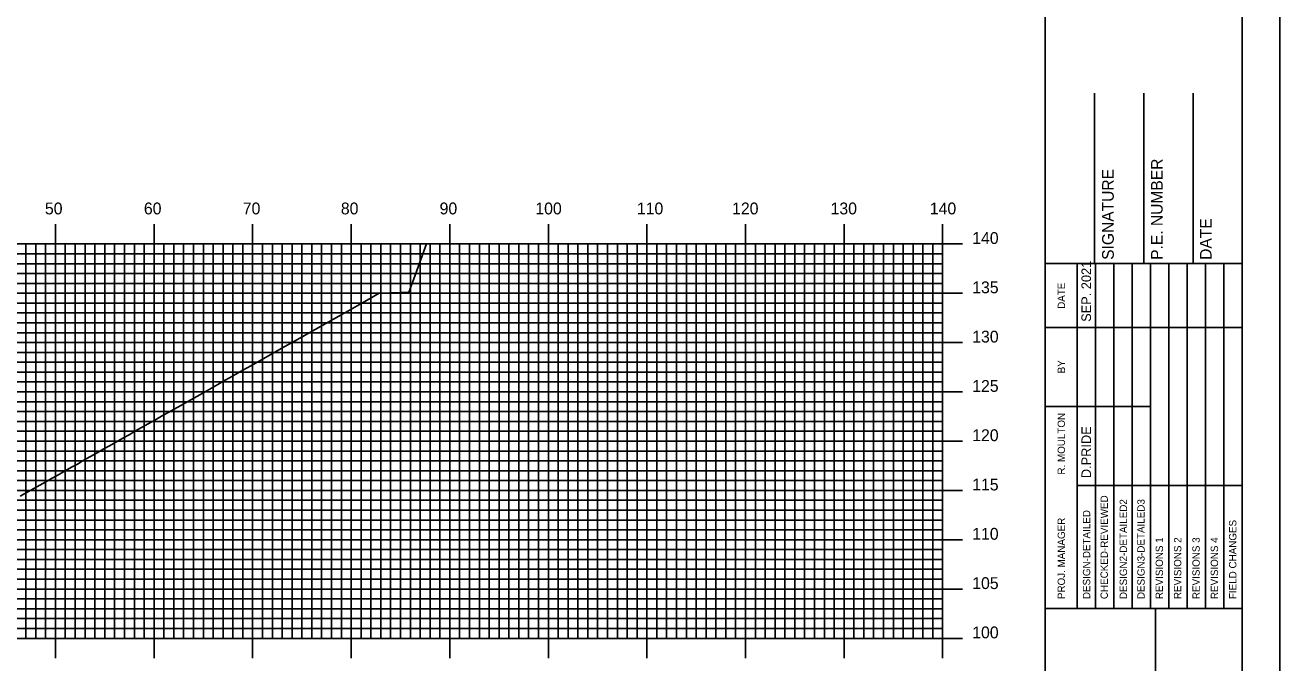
# Model space of a CAD drawing. Extents: x 1685192 to 1685536, y 461260 to 461480.
# Drawn here: x 1685405.1 to 1685532.4, y 461350.6 to 461415.3 of the extents above; entities that cross this region are included whole.
import ezdxf

# ---------------------------------------------------------------- set-up
doc = ezdxf.new("R2010")
doc.units = 0
for name, color, linetype in [('BORDER', 7, 'Continuous'), ('H_V ANNOTATION', 7, 'Continuous'), ('MAJOR', 7, 'Continuous'), ('MINOR', 7, 'Continuous'), ('PLOT BOUNDARY', 7, 'Continuous'), ('S_Roadway_Centerline', 7, 'Continuous')]:
    doc.layers.add(name, color=color, linetype=linetype)

msp = doc.modelspace()

# ---------------------------------------------------------------- linework, layer by layer
at = {"layer": 'BORDER'}
for p, q in [((1685508.63, 461266.07), (1685508.63, 461476.07)), ((1685513.63, 461391.08), (1685513.63, 461408.37)), ((1685518.63, 461391.08), (1685518.63, 461408.37)), ((1685523.63, 461391.08), (1685523.63, 461408.37)), ((1685508.63, 461391.08), (1685528.63, 461391.08)), ((1685508.63, 461356.08), (1685528.63, 461356.08)), ((1685519.81, 461286.08), (1685519.81, 461356.08))]:
    msp.add_line(p, q, dxfattribs=at)
msp.add_lwpolyline([(1685208.63, 461266.07), (1685528.63, 461266.07), (1685528.63, 461476.07), (1685208.63, 461476.07)], close=True, dxfattribs=at)
for points in [[(1685511.86, 461384.58), (1685511.86, 461391.08)], [(1685513.72, 461356.08), (1685513.72, 461391.08)], [(1685515.59, 461391.08), (1685515.59, 461356.08)], [(1685517.45, 461356.08), (1685517.45, 461391.08)], [(1685519.31, 461356.08), (1685519.31, 461391.08)], [(1685521.18, 461356.08), (1685521.18, 461391.08)], [(1685523.04, 461356.08), (1685523.04, 461391.08)], [(1685524.9, 461356.08), (1685524.9, 461391.08)], [(1685526.77, 461356.08), (1685526.77, 461391.08)], [(1685511.86, 461356.08), (1685511.86, 461389.67)], [(1685508.63, 461384.58), (1685528.63, 461384.58)], [(1685508.63, 461376.58), (1685511.86, 461376.58)], [(1685511.86, 461376.58), (1685519.31, 461376.58)], [(1685511.86, 461368.58), (1685528.63, 461368.58)]]:
    msp.add_lwpolyline(points, dxfattribs=at)
at = {"layer": 'MAJOR'}
for p, q in [((1685408.23, 461395.08), (1685408.23, 461393.07)), ((1685418.23, 461395.08), (1685418.23, 461393.07)), ((1685428.23, 461395.08), (1685428.23, 461393.07)), ((1685438.23, 461395.08), (1685438.23, 461393.07)), ((1685448.23, 461395.08), (1685448.23, 461393.07)), ((1685458.23, 461395.08), (1685458.23, 461393.07)), ((1685468.23, 461395.08), (1685468.23, 461393.07)), ((1685478.23, 461395.08), (1685478.23, 461393.07)), ((1685488.23, 461395.08), (1685488.23, 461393.07)), ((1685498.23, 461395.08), (1685498.23, 461393.07)), ((1685218.23, 461393.07), (1685498.23, 461393.07)), ((1685218.23, 461393.07), (1685498.23, 461393.07)), ((1685408.23, 461353.07), (1685408.23, 461393.07)), ((1685418.23, 461353.07), (1685418.23, 461393.07)), ((1685428.23, 461353.07), (1685428.23, 461393.07)), ((1685438.23, 461353.07), (1685438.23, 461393.07)), ((1685448.23, 461353.07), (1685448.23, 461393.07)), ((1685458.23, 461353.07), (1685458.23, 461393.07)), ((1685468.23, 461353.07), (1685468.23, 461393.07)), ((1685478.23, 461353.07), (1685478.23, 461393.07)), ((1685488.23, 461353.07), (1685488.23, 461393.07)), ((1685500.23, 461393.07), (1685496.23, 461393.07)), ((1685498.23, 461353.07), (1685498.23, 461393.07)), ((1685498.23, 461353.07), (1685498.23, 461393.07)), ((1685218.23, 461388.07), (1685498.23, 461388.07)), ((1685500.23, 461388.07), (1685496.23, 461388.07)), ((1685218.23, 461383.07), (1685498.23, 461383.07)), ((1685500.23, 461383.07), (1685496.23, 461383.07)), ((1685218.23, 461378.07), (1685498.23, 461378.07)), ((1685500.23, 461378.07), (1685496.23, 461378.07)), ((1685218.23, 461373.07), (1685498.23, 461373.07)), ((1685500.23, 461373.07), (1685496.23, 461373.07)), ((1685218.23, 461368.07), (1685498.23, 461368.07)), ((1685500.23, 461368.07), (1685496.23, 461368.07)), ((1685218.23, 461363.07), (1685498.23, 461363.07)), ((1685500.23, 461363.07), (1685496.23, 461363.07)), ((1685218.23, 461358.07), (1685498.23, 461358.07)), ((1685500.23, 461358.07), (1685496.23, 461358.07)), ((1685218.23, 461353.07), (1685498.23, 461353.07)), ((1685218.23, 461353.07), (1685498.23, 461353.07)), ((1685408.23, 461351.07), (1685408.23, 461353.07)), ((1685418.23, 461351.07), (1685418.23, 461353.07)), ((1685428.23, 461351.07), (1685428.23, 461353.07)), ((1685438.23, 461351.07), (1685438.23, 461353.07)), ((1685448.23, 461351.07), (1685448.23, 461353.07)), ((1685458.23, 461351.07), (1685458.23, 461353.07)), ((1685468.23, 461351.07), (1685468.23, 461353.07)), ((1685478.23, 461351.07), (1685478.23, 461353.07)), ((1685488.23, 461351.07), (1685488.23, 461353.07)), ((1685500.23, 461353.07), (1685496.23, 461353.07)), ((1685498.23, 461351.07), (1685498.23, 461353.07))]:
    msp.add_line(p, q, dxfattribs=at)
at = {"layer": 'MINOR'}
for p, q in [((1685405.23, 461353.07), (1685405.23, 461393.07)), ((1685406.23, 461353.07), (1685406.23, 461393.07)), ((1685407.23, 461353.07), (1685407.23, 461393.07)), ((1685409.23, 461353.07), (1685409.23, 461393.07)), ((1685410.23, 461353.07), (1685410.23, 461393.07)), ((1685411.23, 461353.07), (1685411.23, 461393.07)), ((1685412.23, 461353.07), (1685412.23, 461393.07)), ((1685413.23, 461353.07), (1685413.23, 461393.07)), ((1685414.23, 461353.07), (1685414.23, 461393.07)), ((1685415.23, 461353.07), (1685415.23, 461393.07)), ((1685416.23, 461353.07), (1685416.23, 461393.07)), ((1685417.23, 461353.07), (1685417.23, 461393.07)), ((1685419.23, 461353.07), (1685419.23, 461393.07)), ((1685420.23, 461353.07), (1685420.23, 461393.07)), ((1685421.23, 461353.07), (1685421.23, 461393.07)), ((1685422.23, 461353.07), (1685422.23, 461393.07)), ((1685423.23, 461353.07), (1685423.23, 461393.07)), ((1685424.23, 461353.07), (1685424.23, 461393.07)), ((1685425.23, 461353.07), (1685425.23, 461393.07)), ((1685426.23, 461353.07), (1685426.23, 461393.07)), ((1685427.23, 461353.07), (1685427.23, 461393.07)), ((1685429.23, 461353.07), (1685429.23, 461393.07)), ((1685430.23, 461353.07), (1685430.23, 461393.07)), ((1685431.23, 461353.07), (1685431.23, 461393.07)), ((1685432.23, 461353.07), (1685432.23, 461393.07)), ((1685433.23, 461353.07), (1685433.23, 461393.07)), ((1685434.23, 461353.07), (1685434.23, 461393.07)), ((1685435.23, 461353.07), (1685435.23, 461393.07)), ((1685436.23, 461353.07), (1685436.23, 461393.07)), ((1685437.23, 461353.07), (1685437.23, 461393.07)), ((1685439.23, 461353.07), (1685439.23, 461393.07)), ((1685440.23, 461353.07), (1685440.23, 461393.07)), ((1685441.23, 461353.07), (1685441.23, 461393.07)), ((1685442.23, 461353.07), (1685442.23, 461393.07)), ((1685443.23, 461353.07), (1685443.23, 461393.07)), ((1685444.23, 461353.07), (1685444.23, 461393.07)), ((1685445.23, 461353.07), (1685445.23, 461393.07)), ((1685446.23, 461353.07), (1685446.23, 461393.07)), ((1685447.23, 461353.07), (1685447.23, 461393.07)), ((1685449.23, 461353.07), (1685449.23, 461393.07)), ((1685450.23, 461353.07), (1685450.23, 461393.07)), ((1685451.23, 461353.07), (1685451.23, 461393.07)), ((1685452.23, 461353.07), (1685452.23, 461393.07)), ((1685453.23, 461353.07), (1685453.23, 461393.07)), ((1685454.23, 461353.07), (1685454.23, 461393.07)), ((1685455.23, 461353.07), (1685455.23, 461393.07)), ((1685456.23, 461353.07), (1685456.23, 461393.07)), ((1685457.23, 461353.07), (1685457.23, 461393.07)), ((1685459.23, 461353.07), (1685459.23, 461393.07)), ((1685460.23, 461353.07), (1685460.23, 461393.07)), ((1685461.23, 461353.07), (1685461.23, 461393.07)), ((1685462.23, 461353.07), (1685462.23, 461393.07)), ((1685463.23, 461353.07), (1685463.23, 461393.07)), ((1685464.23, 461353.07), (1685464.23, 461393.07)), ((1685465.23, 461353.07), (1685465.23, 461393.07)), ((1685466.23, 461353.07), (1685466.23, 461393.07)), ((1685467.23, 461353.07), (1685467.23, 461393.07)), ((1685469.23, 461353.07), (1685469.23, 461393.07)), ((1685470.23, 461353.07), (1685470.23, 461393.07)), ((1685471.23, 461353.07), (1685471.23, 461393.07)), ((1685472.23, 461353.07), (1685472.23, 461393.07)), ((1685473.23, 461353.07), (1685473.23, 461393.07)), ((1685474.23, 461353.07), (1685474.23, 461393.07)), ((1685475.23, 461353.07), (1685475.23, 461393.07)), ((1685476.23, 461353.07), (1685476.23, 461393.07)), ((1685477.23, 461353.07), (1685477.23, 461393.07)), ((1685479.23, 461353.07), (1685479.23, 461393.07)), ((1685480.23, 461353.07), (1685480.23, 461393.07)), ((1685481.23, 461353.07), (1685481.23, 461393.07)), ((1685482.23, 461353.07), (1685482.23, 461393.07)), ((1685483.23, 461353.07), (1685483.23, 461393.07)), ((1685484.23, 461353.07), (1685484.23, 461393.07)), ((1685485.23, 461353.07), (1685485.23, 461393.07)), ((1685486.23, 461353.07), (1685486.23, 461393.07)), ((1685487.23, 461353.07), (1685487.23, 461393.07)), ((1685489.23, 461353.07), (1685489.23, 461393.07)), ((1685490.23, 461353.07), (1685490.23, 461393.07)), ((1685491.23, 461353.07), (1685491.23, 461393.07)), ((1685492.23, 461353.07), (1685492.23, 461393.07)), ((1685493.23, 461353.07), (1685493.23, 461393.07)), ((1685494.23, 461353.07), (1685494.23, 461393.07)), ((1685495.23, 461353.07), (1685495.23, 461393.07)), ((1685496.23, 461353.07), (1685496.23, 461393.07)), ((1685497.23, 461353.07), (1685497.23, 461393.07)), ((1685218.23, 461392.07), (1685498.23, 461392.07)), ((1685498.23, 461392.07), (1685496.23, 461392.07)), ((1685218.23, 461391.07), (1685498.23, 461391.07)), ((1685498.23, 461391.07), (1685496.23, 461391.07)), ((1685218.23, 461390.07), (1685498.23, 461390.07)), ((1685498.23, 461390.07), (1685496.23, 461390.07)), ((1685218.23, 461389.07), (1685498.23, 461389.07)), ((1685498.23, 461389.07), (1685496.23, 461389.07)), ((1685218.23, 461387.07), (1685498.23, 461387.07)), ((1685498.23, 461387.07), (1685496.23, 461387.07)), ((1685218.23, 461386.07), (1685498.23, 461386.07)), ((1685498.23, 461386.07), (1685496.23, 461386.07)), ((1685218.23, 461385.07), (1685498.23, 461385.07)), ((1685218.23, 461384.07), (1685498.23, 461384.07)), ((1685498.23, 461385.07), (1685496.23, 461385.07)), ((1685498.23, 461384.07), (1685496.23, 461384.07)), ((1685218.23, 461382.07), (1685498.23, 461382.07)), ((1685498.23, 461382.07), (1685496.23, 461382.07)), ((1685218.23, 461381.07), (1685498.23, 461381.07)), ((1685498.23, 461381.07), (1685496.23, 461381.07)), ((1685218.23, 461380.07), (1685498.23, 461380.07)), ((1685218.23, 461379.07), (1685498.23, 461379.07)), ((1685498.23, 461380.07), (1685496.23, 461380.07)), ((1685498.23, 461379.07), (1685496.23, 461379.07)), ((1685218.23, 461377.07), (1685498.23, 461377.07)), ((1685498.23, 461377.07), (1685496.23, 461377.07)), ((1685218.23, 461376.07), (1685498.23, 461376.07)), ((1685498.23, 461376.07), (1685496.23, 461376.07)), ((1685218.23, 461375.07), (1685498.23, 461375.07)), ((1685218.23, 461374.07), (1685498.23, 461374.07)), ((1685498.23, 461375.07), (1685496.23, 461375.07)), ((1685498.23, 461374.07), (1685496.23, 461374.07)), ((1685218.23, 461372.07), (1685498.23, 461372.07)), ((1685498.23, 461372.07), (1685496.23, 461372.07)), ((1685218.23, 461371.07), (1685498.23, 461371.07)), ((1685218.23, 461370.07), (1685498.23, 461370.07)), ((1685498.23, 461371.07), (1685496.23, 461371.07)), ((1685498.23, 461370.07), (1685496.23, 461370.07)), ((1685218.23, 461369.07), (1685498.23, 461369.07)), ((1685498.23, 461369.07), (1685496.23, 461369.07)), ((1685218.23, 461367.07), (1685498.23, 461367.07)), ((1685498.23, 461367.07), (1685496.23, 461367.07)), ((1685218.23, 461366.07), (1685498.23, 461366.07)), ((1685218.23, 461365.07), (1685498.23, 461365.07)), ((1685498.23, 461366.07), (1685496.23, 461366.07)), ((1685498.23, 461365.07), (1685496.23, 461365.07)), ((1685218.23, 461364.07), (1685498.23, 461364.07)), ((1685498.23, 461364.07), (1685496.23, 461364.07)), ((1685218.23, 461362.07), (1685498.23, 461362.07)), ((1685498.23, 461362.07), (1685496.23, 461362.07)), ((1685218.23, 461361.07), (1685498.23, 461361.07)), ((1685218.23, 461360.07), (1685498.23, 461360.07)), ((1685498.23, 461361.07), (1685496.23, 461361.07)), ((1685498.23, 461360.07), (1685496.23, 461360.07)), ((1685218.23, 461359.07), (1685498.23, 461359.07)), ((1685498.23, 461359.07), (1685496.23, 461359.07)), ((1685218.23, 461357.07), (1685498.23, 461357.07)), ((1685218.23, 461356.07), (1685498.23, 461356.07)), ((1685498.23, 461357.07), (1685496.23, 461357.07)), ((1685498.23, 461356.07), (1685496.23, 461356.07)), ((1685218.23, 461355.07), (1685498.23, 461355.07)), ((1685498.23, 461355.07), (1685496.23, 461355.07)), ((1685218.23, 461354.07), (1685498.23, 461354.07)), ((1685498.23, 461354.07), (1685496.23, 461354.07))]:
    msp.add_line(p, q, dxfattribs=at)
at = {"layer": 'PLOT BOUNDARY'}
msp.add_lwpolyline([(1685192.44, 461259.95), (1685532.44, 461259.95), (1685532.44, 461479.95), (1685192.44, 461479.95)], close=True, dxfattribs=at)
at = {"layer": 'S_Roadway_Centerline'}
msp.add_lwpolyline([(1685404.66, 461367.48), (1685405.2, 461367.78), (1685405.74, 461368.09), (1685407.26, 461368.95), (1685407.82, 461369.27), (1685408.4, 461369.59), (1685409.86, 461370.42), (1685410.45, 461370.75), (1685411.05, 461371.1), (1685412.46, 461371.89), (1685413.07, 461372.24), (1685413.7, 461372.6), (1685415.05, 461373.36), (1685415.7, 461373.72), (1685416.35, 461374.1), (1685417.65, 461374.84), (1685418.32, 461375.21), (1685419, 461375.6), (1685420.26, 461376.31), (1685420.95, 461376.69), (1685421.65, 461377.09), (1685422.86, 461377.78), (1685423.57, 461378.18), (1685424.3, 461378.59), (1685425.46, 461379.25), (1685426.2, 461379.66), (1685426.94, 461380.09), (1685428.06, 461380.72), (1685428.82, 461381.14), (1685429.59, 461381.58), (1685430.66, 461382.19), (1685431.44, 461382.63), (1685432.23, 461383.08), (1685433.27, 461383.66), (1685436.98, 461385.75), (1685437.18, 461385.86), (1685437.32, 461385.94), (1685437.65, 461386.13), (1685439.53, 461387.2), (1685440.08, 461387.51), (1685441.08, 461388.07), (1685442.24, 461388.11), (1685444.08, 461388.17), (1685444.17, 461388.42), (1685444.18, 461388.45), (1685444.58, 461389.54), (1685445.87, 461393.07)], dxfattribs=at)

# ---------------------------------------------------------------- texts
at = {"layer": 'BORDER'}
for s, height, p in [('P.E. NUMBER', 1.1811, (1685520.55, 461391.46)), ('SIGNATURE', 1.181, (1685515.59, 461391.46)), ('DATE', 1.181, (1685525.51, 461391.46)), ('SEP. 2021', 0.969, (1685513.28, 461385.17)), ('DATE', 0.743, (1685510.64, 461386.49)), ('BY', 0.743, (1685510.64, 461379.95)), ('R. MOULTON', 0.745, (1685510.64, 461369.68)), ('D.PRIDE', 0.969, (1685513.28, 461369.32)), ('CHECKED-REVIEWED', 0.7455, (1685514.99, 461357.05)), ('DESIGN2-DETAILED2', 0.7455, (1685516.93, 461357.05)), ('DESIGN3-DETAILED3', 0.7455, (1685518.72, 461357.05)), ('PROJ. MANAGER', 0.7455, (1685510.64, 461357.05)), ('DESIGN-DETAILED', 0.7455, (1685513.2, 461357.05)), ('FIELD CHANGES', 0.7455, (1685528.03, 461357.05)), ('REVISIONS 1', 0.7455, (1685520.58, 461357.05)), ('REVISIONS 2', 0.7455, (1685522.44, 461357.05)), ('REVISIONS 3', 0.7455, (1685524.31, 461357.05)), ('REVISIONS 4', 0.7455, (1685526.17, 461357.05))]:
    msp.add_text(s, height=height, rotation=90, dxfattribs=at).set_placement(p)
at = {"layer": 'H_V ANNOTATION'}
for s, p in [('50', (1685407.16, 461396.07)), ('60', (1685417.2, 461396.07)), ('70', (1685427.23, 461396.07)), ('80', (1685437.18, 461396.07)), ('90', (1685447.2, 461396.07)), ('100', (1685456.91, 461396.07)), ('110', (1685467.21, 461396.07)), ('120', (1685476.87, 461396.07)), ('130', (1685486.86, 461396.07)), ('140', (1685496.93, 461396.07)), ('140', (1685501.23, 461393.07)), ('135', (1685501.23, 461388.07)), ('130', (1685501.23, 461383.07)), ('125', (1685501.23, 461378.07)), ('120', (1685501.23, 461373.07)), ('115', (1685501.23, 461368.07)), ('110', (1685501.23, 461363.07)), ('105', (1685501.23, 461358.07)), ('100', (1685501.23, 461353.07))]:
    msp.add_text(s, height=1.2, dxfattribs=at).set_placement(p)

doc.saveas('drawing.dxf')
